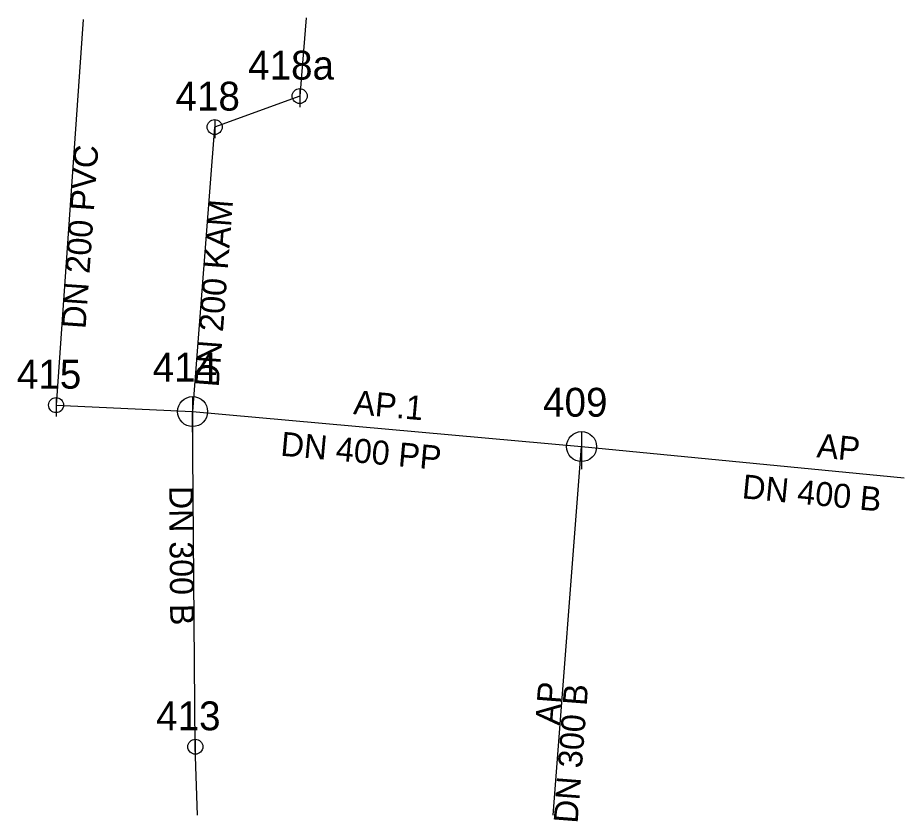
# Model space of a CAD drawing. Extents: x -467730 to -467670.9, y -1119251.4 to -1119197.8.
import ezdxf

# ---------------------------------------------------------------- set-up
doc = ezdxf.new("R2010")
doc.units = 0
for name, color, linetype in [('_pripojka_kanal_jednotna_prevzato_z_dokumentace_', 7, 'Continuous'), ('_pripojka_kanal_jednotna_priblizne_', 7, 'Continuous'), ('_sachta_kanal_', 7, 'Continuous'), ('_stoka_jednotna_smvak_prevzato_z_dokumentace_', 7, 'Continuous'), ('Default', 7, 'Continuous'), ('MoLevel 119', 7, 'Continuous'), ('MoLevel 120', 7, 'Continuous'), ('MoLevel 126', 7, 'Continuous'), ('MoLevel 57', 7, 'Continuous'), ('MoLevel 68', 7, 'Continuous'), ('MoLevel 69', 7, 'Continuous')]:
    doc.layers.add(name, color=color, linetype=linetype)

# ---------------------------------------------------------------- blocks, each defined once
blk = doc.blocks.new('_sachta_kanal_prip_')
at = {"layer": 'Default'}
blk.add_line((0, 0.00005), (0, -0.000075), dxfattribs=at)
blk.add_circle((0, 0), 0.00005, dxfattribs=at)
blk = doc.blocks.new('_sachta_kanal_prevzato_z_dokumentace_')
at = {"layer": 'Default'}
blk.add_line((0, 0.00005), (0, -0.000075), dxfattribs=at)
blk.add_circle((0, 0), 0.00005, dxfattribs=at)

msp = doc.modelspace()

# ---------------------------------------------------------------- linework, layer by layer
at = {"layer": '_pripojka_kanal_jednotna_prevzato_z_dokumentace_'}
for p, q in [((-467710.803, -1119197.813), (-467711.23, -1119203.041)), ((-467725.66, -1119197.93), (-467727.479, -1119223.67)), ((-467711.23, -1119203.041), (-467716.9, -1119205.11)), ((-467716.9, -1119205.11), (-467718.37, -1119224.1)), ((-467727.479, -1119223.67), (-467718.37, -1119224.1)), ((-467718.19, -1119246.47), (-467718.37, -1119224.1))]:
    msp.add_line(p, q, dxfattribs=at)
at = {"layer": '_pripojka_kanal_jednotna_priblizne_'}
msp.add_line((-467718.035, -1119251.04), (-467718.189, -1119246.469), dxfattribs=at)
at = {"layer": '_stoka_jednotna_smvak_prevzato_z_dokumentace_'}
for p, q in [((-467718.37, -1119224.1), (-467692.43, -1119226.439)), ((-467694.325, -1119251.04), (-467692.43, -1119226.439)), ((-467692.43, -1119226.439), (-467670.908, -1119228.514))]:
    msp.add_line(p, q, dxfattribs=at)

# ---------------------------------------------------------------- block references
at = {"layer": 'MoLevel 119', "xscale": 20000, "yscale": 20000}
for p in [(-467718.369, -1119224.099), (-467692.429, -1119226.439)]:
    msp.add_blockref('_sachta_kanal_prevzato_z_dokumentace_', p, dxfattribs=at)
at = {"layer": 'MoLevel 57', "xscale": 10000, "yscale": 10000}
for p in [(-467711.23, -1119203.041), (-467716.899, -1119205.11), (-467727.479, -1119223.669), (-467718.189, -1119246.469)]:
    msp.add_blockref('_sachta_kanal_prip_', p, dxfattribs=at)

# ---------------------------------------------------------------- texts
at = {"layer": '_sachta_kanal_'}
for s, p in [('418a', (-467714.669, -1119201.941)), ('418', (-467719.513, -1119204.01)), ('415', (-467730.093, -1119222.569)), ('413', (-467720.803, -1119245.369))]:
    msp.add_text(s, height=1.9259, dxfattribs=at).set_placement(p)
at = {"layer": 'MoLevel 120'}
for s, p in [('414', (-467721.029, -1119222.099)), ('409', (-467694.997, -1119224.439))]:
    msp.add_text(s, height=1.9259, dxfattribs=at).set_placement(p)
at = {"layer": 'MoLevel 126'}
for s, rotation, p in [('DN 200 PVC', 85.95773, (-467725.513, -1119218.613)), ('DN 200 KAM', 85.57361, (-467716.636, -1119222.501)), ('DN 300 B', 270.46102, (-467719.935, -1119229.069))]:
    msp.add_text(s, height=1.6049, rotation=rotation, dxfattribs=at).set_placement(p)
at = {"layer": 'MoLevel 68'}
for s, rotation, p in [('DN 400 PP', 354.8476, (-467712.547, -1119227.037)), ('DN 400 B', 354.49292, (-467681.774, -1119229.879)), ('DN 300 B', 85.59535, (-467692.698, -1119251.618))]:
    msp.add_text(s, height=1.6049, rotation=rotation, dxfattribs=at).set_placement(p)
at = {"layer": 'MoLevel 69'}
for s, rotation, p in [('AP.1', 354.8476, (-467707.684, -1119224.264)), ('AP', 354.49292, (-467676.789, -1119227.147)), ('AP', 85.59535, (-467693.926, -1119245.056))]:
    msp.add_text(s, height=1.6049, rotation=rotation, dxfattribs=at).set_placement(p)

doc.saveas('drawing.dxf')
